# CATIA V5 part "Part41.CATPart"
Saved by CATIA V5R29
Part number: spur gear_iso_ISO - Spur gear 0.5M 29T 20PA 6FW ---S29A75H50L3.0N
Revision: ANY
Definition: UNKNOWN
Nomenclature: spur gear_iso_ISO - Spur gear 0.5M 29T 20PA 6FW ---S29A75H50L3.0N
Source: Unknown
Bounding box of the stored display mesh (mm): x 0 to 6, y -7.749 to 7.719, z -7.745 to 7.745
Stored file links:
  C:\Users\Administrator\Desktop\프로젝트\Gripper\Part41.CATPart
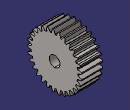
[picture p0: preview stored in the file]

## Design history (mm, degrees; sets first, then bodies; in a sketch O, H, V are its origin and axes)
Body1 "Bore" (main body)
  Solid1: solid without history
